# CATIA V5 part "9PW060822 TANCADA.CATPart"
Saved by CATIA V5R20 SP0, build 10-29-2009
Part number: 9PW060822 TANCADA
Revision: ANY
Definition: UNKNOWN
Nomenclature: 9PW060822 TANCADA
Source: Unknown
Bounding box of the stored display mesh (mm): x -124.996 to 0, y -5.5 to 3.5, z -4.1 to 4.1
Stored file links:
  C:\Users\Utente\Desktop\IO LAVORO\3D X SITO CF\CUMSA\3D files PW\pw060822\pw060822_injection\9PW060822 TANCADA.CATPart
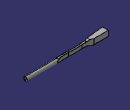
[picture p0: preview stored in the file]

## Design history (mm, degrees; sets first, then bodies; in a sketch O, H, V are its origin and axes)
Body1 "Chaflán1" (main body)
  Solid1: solid without history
